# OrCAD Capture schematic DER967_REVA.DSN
size C; title: DER 967 - 5V 1A; rev: B
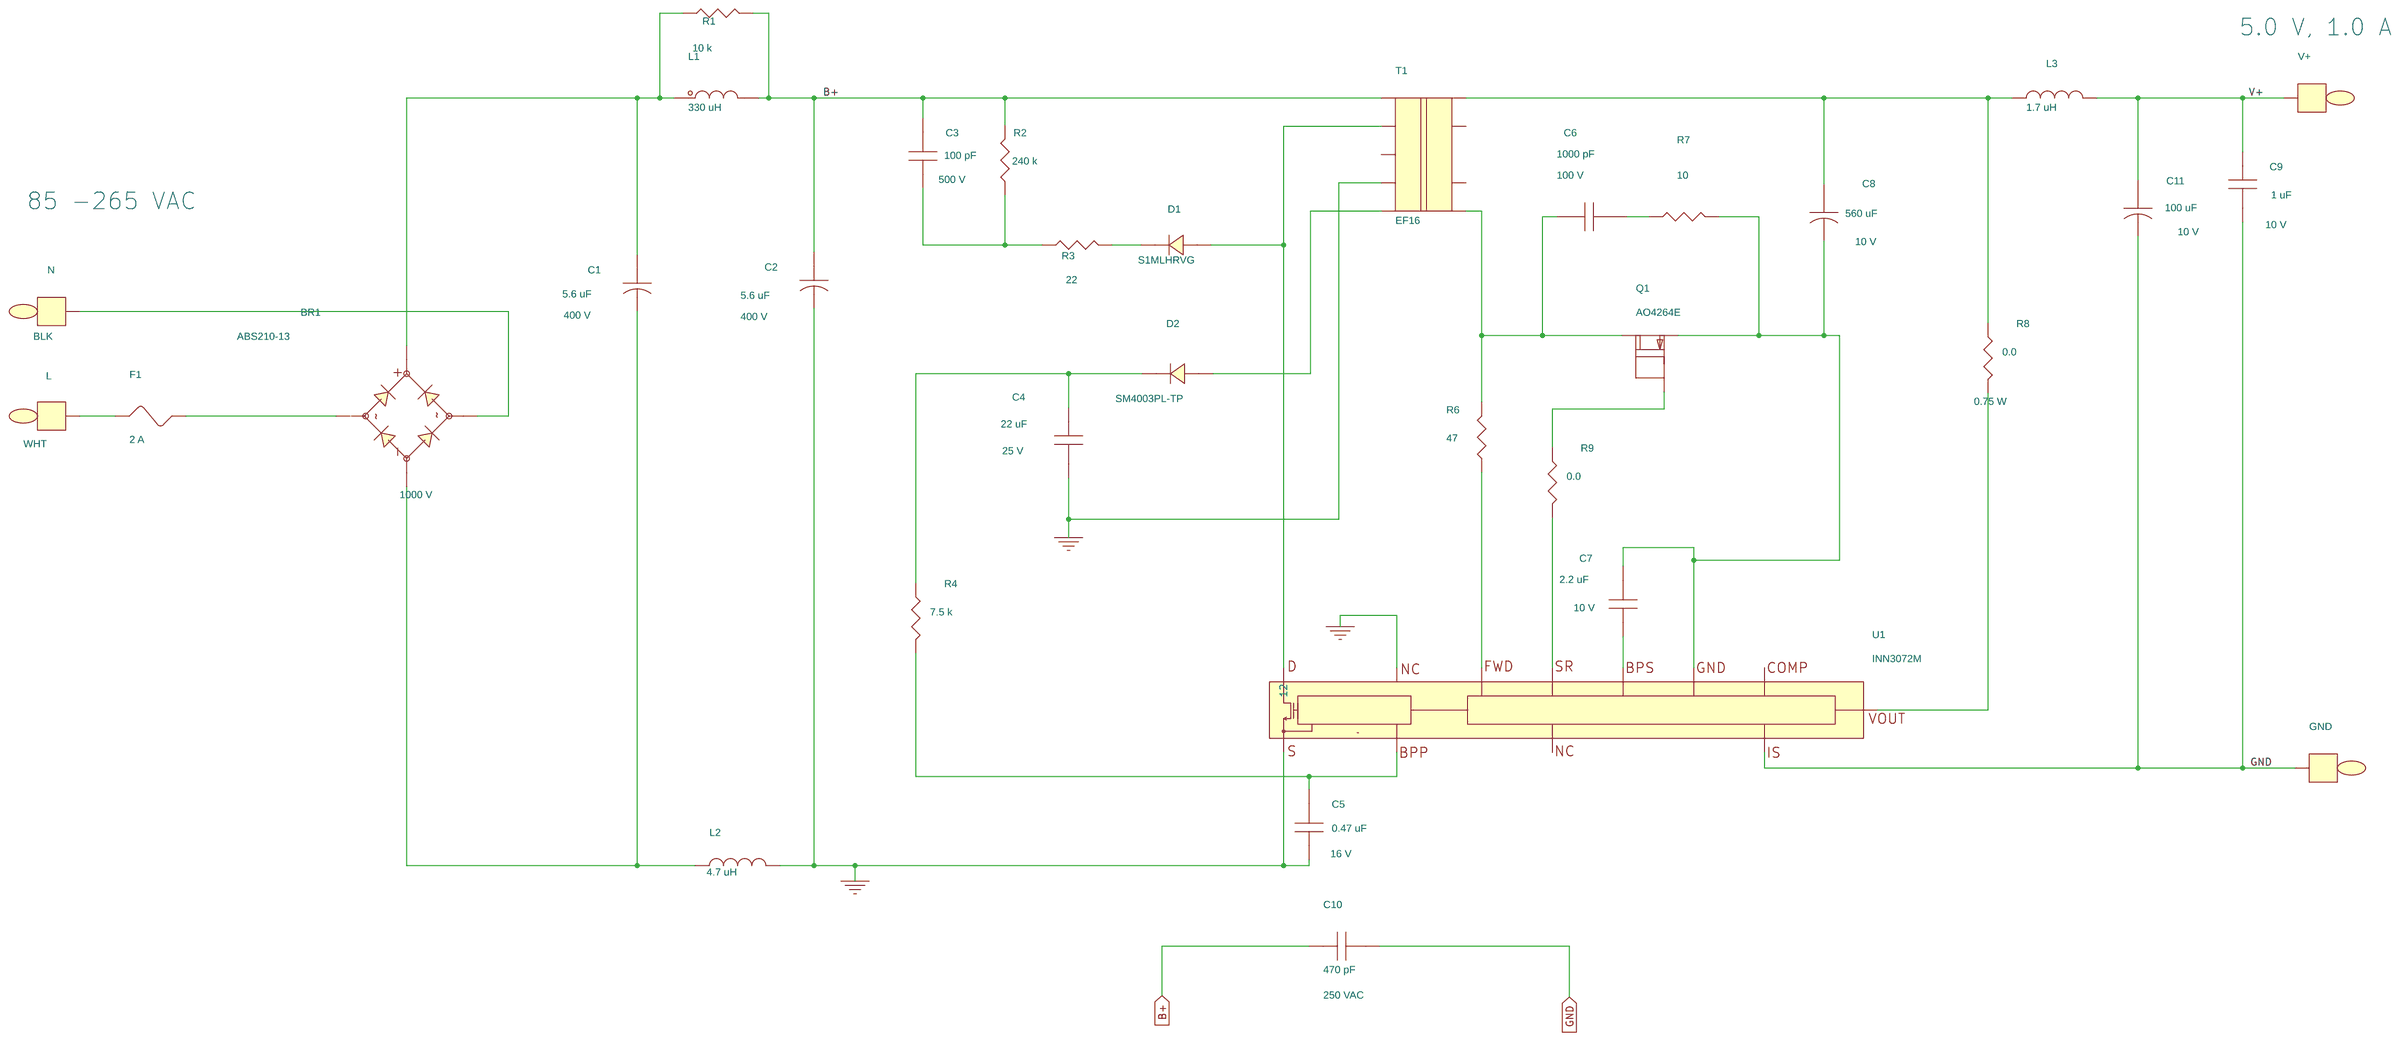
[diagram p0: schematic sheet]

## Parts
BR1  ABS210-13  [pismd_SOPA-4]
C1  5.6 uF  [pipolcapcyld315ls138d030]
C2  5.6 uF  [pipolcapcyld315ls138d030]
C3  100 pF  [pismc0805]
C4  22 uF  [pismc0805]
C5  0.47 uF  [pismc0603]
C6  1000 pF  [pismc0603]
C7  2.2 uF  [pismc0603]
C8  560 uF  [pipolcapcyld250ls100030]
C9  1 uF  [pismc0805]
C10  470 pF  [pinpcaprad374x275ls394d040]
C11  100 uF  [pipolcapclyd248ls098028]
D1  S1MLHRVG  [pi_sm_sod-123_12]
D2  SM4003PL-TP  [pi_sm_sod-123_12]
F1  2 A  [pi_rst_microfuse]
GND  GND  [pitpkeystone100x100]
L  WHT  [pitpkeystone100x100]
L1  330 uH  [pi_choke_RL5480-2_d2]
L2  4.7 uH  [pismr0805]
L3  1.7 uH  [pichoke6mm2pin4mmLSd030]
N  BLK  [pitpkeystone100x100]
Q1  AO4264E  [pismso8]
R1  10 k  [pismr1206]
R2  240 k  [pismr0805]
R3  22  [pismr0805]
R4  7.5 k  [pismr0603]
R6  47  [pismr0805]
R7  10  [pismr0805]
R8  0.0  [pismr2010]
R9  0.0  [pismr0805]
T1  EF16  [pi_bobbin_ef16_9p_5x4_lnk574a]
U1  INN3072M  [PI_SM_MinSOP16A_1]
V+  RED  [pitpkeystone100x100]

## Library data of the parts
BR1 = DIODE_BRIDGE_+~~-: ALT_SYMBOLS: pismd_SOPA-4a,pi_sm_soic4_slot; Disp_Voltage: 1000 V; FPLIST: pismd_SOPA-4,pismd_SOPA-4a,pi_sm_soic4_slot; Part Number: 15-01254-00
C1 C2 = CAP_POL: ALT_SYMBOLS: pipolcapcyld315ls138d030h; Disp_Voltage: 400 V; FPLIST: pipolcapcyld315ls138d030,pipolcapcyld315ls138d030h; Part Number: 20-08972-00; Voltage: 400 V
C3 = CAP_NP: Disp_Voltage: 500 V; Part Number: 20-01717-00; Voltage: 500 V
C4 = CAP_NP: Disp_Voltage: 25 V; Part Number: 20-01596-00; Voltage: 25 V
C5 = CAP_NP: Disp_Voltage: 16 V; Part Number: 20-08990-00; Voltage: 16 V
C6 = CAP_NP: Disp_Voltage: 100 V; Part Number: 20-00712-00; Voltage: 100 V
C7 = CAP_NP: ALT_SYMBOLS: pismc0603_1; Disp_Voltage: 10 V; FPLIST: pismc0603,pismc0603_1; Part Number: 20-08740-00; Voltage: 10V
C8 = CAP_POL: Disp_Voltage: 10 V; Part Number: 23-00077-00; Voltage: 10 V
C9 = CAP_NP: Disp_Voltage: 10 V; Part Number: 20-08953-00; Voltage: 10 V
C10 = CAP_NP: Disp_Voltage: 250 VAC; Part Number: 20-01595-00; Voltage: 250 VAC
C11 = CAP_POL: ALT_SYMBOLS: pipolcapclyd6p3x9mm_h; Disp_Voltage: 10 V; FPLIST: pipolcapclyd248ls098028,pipolcapclyd6p3x9mm_h; Part Number: 20-01569-00; Voltage: 10 V
D1 = DIODE: Disp_Voltage: 1 kV; Part Number: 15-01663-00
D2 = DIODE: Part Number: 15-01052-00
F1 = FUSE: ALT_SYMBOLS: pirstmicrofusehoz; FPLIST: pi_rst_microfuse,pirstmicrofusehoz; Part Number: 40-00021-00
GND N = TESTPOINT: Part Number: 35-00079-00
L = TESTPOINT: Part Number: 35-00081-00
L1 = INDUCTOR_dot2: ALT_SYMBOLS: pi_choke_RL5480-2H_d2; FPLIST: pi_choke_RL5480-2_d2,pi_choke_RL5480-2H_d2; Part Number: 30-00307-00
L2 = INDUCTOR: Part Number: 30-00372-00
L3 = INDUCTOR: Part Number: 30-00451-00
Q1 = FET_P_SGD_123_4_5678: Part Number: 50-00368-00
R1 = R: Part Number: 05-01376-00
R2 = R: Part Number: 05-01576-00
R3 = R: Part Number: 05-01479-00
R4 = R: Disp_Tol: 1%; Part Number: 05-01162-00
R6 = R: Part Number: 05-01487-00
R7 = R: Disp_Tol: 1%; Part Number: 05-00492-00
R8 = R: Disp_Power: 0.75 W; Part Number: 05-06444-00
R9 = R: ALT_SYMBOLS: pismr0805_1; FPLIST: pismr0805,pismr0805_1; Part Number: 05-03159-00
T1 = BEF16_H_9P_5x4: Part Number: 25-01030-00
U1 = Inno3TNMinSOP16_5: Part Number: 10-01311-00
V+ = TESTPOINT: Part Number: 35-00080-00

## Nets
GND: C9.2 C10.2 C11.2 GND.1 U1.1
0: C2.2 C4.2 C5.1 L2.2 T1.4 U1.9 U1.11
B+: C2.1 C3.2 C10.1 L1.1 R1.2 R2.2 T1.1
V+: C9.1 C11.1 L3.2 V+.1
N2618450: C8.1 L3.1 R8.1 T1.9
N2618494: BR1.1 C1.1 L1.2 R1.1
N2618826: C3.1 R2.1 R3.2
N2618846: C6.1 Q1.5(D) R6.1 T1.6
N2618854: C6.2 R7.2
N2618858: C7.2 C8.2 Q1.1(S) R7.1 U1.2
N2618940: BR1.4 C1.2 L2.1
N2618994: D1.1 R3.1
N2618998: D1.2 T1.2 U1.16(12)
N2619084: C4.1 D2.1 R4.1
N2619088: Q1.4(G) R9.1
N2619426: C5.2 R4.2 U1.10
N2626861: BR1.3 N.1
N11196837: R8.2 U1.6
N11197056: R6.2 U1.7
N11221476: D2.2 T1.5
N11228330: F1.2 L.1
N11228899: BR1.2 F1.1
N11236373: C7.1 U1.4
N11252892: R9.2 U1.5

Not connected (* = marked no-connect by the designer): Q1 2(S2) 3(S3) 6(D6) 7(D7) 8(D8); T1 3 7 8; U1 3 8

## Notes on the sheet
- 5.0 V, 1.0 A
- 85 -265 VAC
